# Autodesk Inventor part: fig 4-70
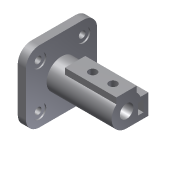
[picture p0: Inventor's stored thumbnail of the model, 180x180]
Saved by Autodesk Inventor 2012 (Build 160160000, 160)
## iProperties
Shininess: 77.0
Length Units: 11269
Angle Units: 11279
Time Units: 11290
Mass Units: 11283
Length Display Precision: 3
Angle Display Precision: 2
Created: 2001-12
Part Number: fig 4-70
Document SubType Name: Modeling
Designer: Renu Muthoo
Density: 1 g/cm^3
Material: Default
Density: 0.0
Volumn: 0.0
Area: 0.0
PropertySet Name: Model Information
Control State: 0
Master: False
Checked Out: False
Author: Renu Muthoo
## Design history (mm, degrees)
node "Sketch1"
sketch "Sketch2"
  geometry: L1 (24.44, 30.488)-(-40.56, 30.488); L2 (-60.56, 10.488)-(-60.56, -54.512); L3 (-40.56, -74.512)-(24.44, -74.512); L4 (44.44, -54.512)-(44.44, 10.488); A1 r 20 centre (24.44, 10.488) between (44.44, 10.488) and (24.44, 30.488); A2 r 20 centre (-40.56, 10.488) between (-40.56, 30.488) and (-60.56, 10.488); A3 r 20 centre (-40.56, -54.512) between (-60.56, -54.512) and (-40.56, -74.512); A4 r 20 centre (24.44, -54.512) between (24.44, -74.512) and (44.44, -54.512); 2 further points
  constraints: 8 end point, 8 point on circle, 8 tangent, 4 centre point, 4 point on line, 3 equal radius, 2 parallel, 2 perpendicular, 1 horizontal
  dimensions: "d1" = 20 radius of A1; "d2" = 105 distance between parallel lines of L2 L4
extrude "Extrusion1" new body sketch "Sketch2" distance "d3" = 12; taper "d4" = 0 deg
sketch "Sketch3"
  geometry: A1 r 20 centre (-24.44, 10.488) between (-24.44, 30.488) and (-44.44, 10.488) reference; A2 r 20 centre (-24.44, -54.512) between (-44.44, -54.512) and (-24.44, -74.512) reference; A3 r 20 centre (40.56, -54.512) between (40.56, -74.512) and (60.56, -54.512) reference; A4 r 20 centre (40.56, 10.488) between (60.56, 10.488) and (40.56, 30.488) reference
hole "Hole1" sketch "Sketch3" at (-24.44, 10.488), (-24.44, -54.512), (40.56, 10.488), (40.56, -54.512) diameter "d5" = 10; stored, may be unused: countersink angle "d9" = 82 deg, drill point angle "d11" = 118 deg; dims "d6" = 6, "d7" = 20, "d8" = 2, "d10" = 8
sketch "Sketch4"
  geometry: L1 (-24.44, 30.488)-(40.56, 30.488) reference; L2 (-44.44, -54.512)-(-44.44, 10.488) reference; C1 r 22 at (8.06, -22.012)
  constraints: 1 centre point
  dimensions: "d12" = 52.5 distance from line of L2 C1.centre; "d13" = 52.5 distance from line of L1 C1.centre; "d14" = 44 diameter of C1
extrude "Extrusion2" join sketch "Sketch4" distance "d15" = 96; taper "d16" = 0 deg
sketch "Sketch5"
  geometry: L1 (-15, 16.093)-(15, 16.093); L2 (15, 16.093)-(15, 25); L3 (15, 25)-(-15, 25); L4 (-15, 25)-(-15, 16.093); 1 further point
  constraints: 8 end point, 2 parallel, 1 horizontal, 1 perpendicular, 2 other
  dimensions: "d17" = 30 distance of L2.end L3.end; "d18" = 25 distance from line of point (0, 0) L3; "d19" = 15 distance from line of point (0, 0) L4
extrude "Extrusion3" join sketch "Sketch5" distance "d20" = 76; taper "d21" = 0 deg
sketch "Sketch6"
  geometry: L1 (8, -44.012)-(40.06, -44.012); L2 (40.06, -44.012)-(40.06, -14.012); L3 (40.06, -14.012)-(8, -14.012); L4 (8, -14.012)-(8, -44.012); A1 r 22 centre (8.06, -22.012) between (-6.94, -5.918) and (23.06, -5.918) reference
  constraints: 8 end point, 2 parallel, 1 horizontal, 1 perpendicular, 1 tangent
  dimensions: "d22" = 32 distance from line of A1.centre L2; "d23" = 30 distance of L1.end L2.end
extrude "Extrusion4" join sketch "Sketch6" distance "d24" = 57; taper "d25" = 0 deg
sketch "Sketch7"
  geometry: L1 (25.06, -20.012)-(33.06, -20.012); L2 (33.06, -20.012)-(33.06, -36.012); L3 (33.06, -36.012)-(25.06, -36.012); L4 (25.06, -36.012)-(25.06, -20.012); A1 r 22 centre (8.06, -22.012) between (-6.94, -5.918) and (8, -44.012) reference
  constraints: 8 end point, 2 parallel, 1 horizontal, 1 perpendicular
  dimensions: "d26" = 8 distance of L2.end L3.end; "d27" = 16 distance of L1.end L2.end; "d28" = 25 distance from line of A1.centre L2; "d29" = 2 vertical distance of A1.centre L1.start
extrude "Extrusion5" cut sketch "Sketch7" distance "d30" = 35; taper "d31" = 0 deg
sketch "Sketch8"
  geometry: A1 r 22 centre (8.06, -22.012) between (-6.94, -5.918) and (8, -44.012) reference
hole "Hole2" sketch "Sketch8" at (8.06, -22.012) diameter "d32" = 20; stored, may be unused: countersink angle "d36" = 82 deg, drill point angle "d38" = 0 deg; dims "d33" = 6, "d34" = 20, "d35" = 2, "d37" = 96
sketch "Sketch9"
  geometry: L1 (0, 0)-(0, 76) reference; L2 (30, 0)-(0, 0) reference; 2 further points
  dimensions: "d39" = 20 distance from line of L2 point (15, 20); "d40" = 15 distance from line of L1 point (15, 20); "d41" = 30 distance of point (15, 50) point (15, 20)
hole "Hole3" sketch "Sketch9" at (15, 20), (15, 50) diameter "d42" = 12; stored, may be unused: countersink angle "d46" = 82 deg, drill point angle "d48" = 0 deg; dims "d43" = 6, "d44" = 20, "d45" = 2, "d47" = 25
sketch "Sketch10"
  geometry: L1 (30, 0)-(0, 0) reference; L2 (30, 0)-(30, 57) reference; 2 further points
  dimensions: "d49" = 15 distance from line of L1 point (15, 15); "d50" = 15 distance from line of L2 point (15, 15); "d51" = 22 distance of point (15, 37) point (15, 15)
hole "Hole4" sketch "Sketch10" at (15, 15), (15, 37) diameter "d52" = 10; stored, may be unused: countersink angle "d56" = 82 deg, drill point angle "d58" = 0 deg; dims "d53" = 6, "d54" = 20, "d55" = 2, "d57" = 7
body "Solid1"
